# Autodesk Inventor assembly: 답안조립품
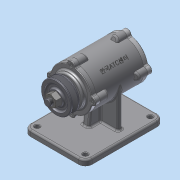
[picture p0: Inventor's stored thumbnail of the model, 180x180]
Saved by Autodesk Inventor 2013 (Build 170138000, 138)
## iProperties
Created: 2015-12
Part Number: 답안조립품
Document SubType Name: Assembly
Designer: dgall
Author: dgall
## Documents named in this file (11)
- C:\Users\dgall\Desktop\451207V1020\답안조립품.iam
- C:\Users\dgall\Desktop\451207V1020\본체.ipt
- C:\Users\dgall\Desktop\451207V1020\V-벨트풀리.ipt
- C:\Users\dgall\Desktop\451207V1020\너트 M12x1.25.ipt
- C:\Users\dgall\Desktop\451207V1020\베어링 6204.ipt
- C:\Users\dgall\Desktop\451207V1020\볼트 M4 x 12.ipt
- C:\Users\dgall\Desktop\451207V1020\오일실.ipt
- C:\Users\dgall\Desktop\451207V1020\축.ipt
- C:\Users\dgall\Desktop\451207V1020\커버.ipt
- C:\Users\dgall\Desktop\451207V1020\커버2.ipt
- C:\Users\dgall\Desktop\451207V1020\키(4 x 4 x 12).ipt
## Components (6 placed, 5 different names)
1. V-벨트풀리:1
2. KS B 1012 클래스 1 일반 - 미터 M12x1.25:1
3. KS B 2023 6204 - 20 x 47 x 14:1
4. KS B 2804 D D - 20 32 8:1
5. KS B 1311 (I) 4 x 4 x 12:1 — 각도:1
6. KS B 2023 6204 - 20 x 47 x 14:2
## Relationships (1: Angle 1)
- 각도:1 [Angle]: KS B 1311 (I) 4 x 4 x 12:1
